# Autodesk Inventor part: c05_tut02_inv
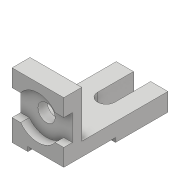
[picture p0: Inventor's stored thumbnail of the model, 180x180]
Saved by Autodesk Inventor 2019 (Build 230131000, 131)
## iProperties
Created: 2017-04
Part Number: c05_tut02_inv
Material: Generic
Document SubType Name: Modeling
Designer: CADCIM 00
Density: 1 g/cm^3
Appearance: Default
Author: CADCIM 00
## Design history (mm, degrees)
sketch "Sketch1"
  geometry: L1 (0, 0)-(0, 90); L2 (0, 90)-(25, 90); L3 (25, 90)-(25, 25); L4 (25, 25)-(145, 25); L5 (145, 25)-(145, 0); L6 (145, 0)-(0, 0)
  constraints: 12 end point, 6 perpendicular, 1 vertical
  dimensions: "d0" = 90 distance of L1.start L1.end; "d1" = 25 distance of L1.end L2.end; "d2" = 145 distance of L5.end L1.start
extrude "Extrusion1" new body sketch "Sketch1" stored distance "d3" = 72; taper "d4" = 0 deg
sketch "Sketch2"
  geometry: L1 (0, 0)-(0, 145) reference; L2 (0, 0)-(-6, 0); L3 (-6, 0)-(-6, 72); L4 (-6, 72)-(0, 72); L5 (0, 72)-(0, 0)
  constraints: 8 end point, 2 parallel, 1 horizontal, 1 perpendicular
  dimensions: "d5" = 72 distance between parallel lines of L4 L2; "d6" = 6 distance between parallel lines of L1 L3
extrude "Extrusion2" cut sketch "Sketch2" distance "d7" = 50; taper "d8" = 0 deg
sketch "Sketch3"
  geometry: L1 (0, 0)-(0, -65) reference; L2 (72, -65)-(72, 0) reference; L3 (72, -24)-(72, -60); L4 (0, -60)-(0, -24); L5 (0, -24)-(12, -24); L6 (60, -24)-(72, -24); L7 (72, -60)-(60, -60); L8 (12, -60)-(0, -60); L9 (72, -90)-(22, -90) reference; L10 (0, -90)-(22, -90) reference; A1 r 30 centre (36, -42) between (12, -60) and (60, -60); A2 r 30 centre (36, -42) between (60, -24) and (12, -24); 1 further point
  constraints: 12 end point, 5 parallel, 4 point on circle, 2 centre point, 2 collinear, 2 horizontal, 2 perpendicular, 2 point on line, 1 concentric
  dimensions: "d9" = 30 radius of A2; "d10" = 48 distance from line of L9 A1.centre; "d11" = 36 distance from line of L1 A1.centre; "d12" = 36 distance between parallel lines of L8 L5; "d13" = 30 distance between parallel lines of L10 L8
extrude "Extrusion3" cut sketch "Sketch3" distance "d14" = 12; taper "d15" = 0 deg
sketch "Sketch4"
  geometry: C1 r 12 at (36, -42); A1 r 30 centre (36, -42) between (60, -24) and (12, -24) reference; 1 further point
  constraints: 1 centre point, 1 concentric
  dimensions: "d16" = 24 diameter of C1
extrude "Extrusion4" cut sketch "Sketch4" stored distance "d17" = 12; taper "d18" = 0 deg
sketch "Sketch5"
  geometry: L1 (36, 119.693)-(36, 70); L2 (24, 119.693)-(24, 70); L3 (48, 70)-(48, 120); L4 (72, 120)-(0, 120) reference; L5 (24.004, 120)-(48, 120); L6 (72, 120)-(0, 120) reference; L7 (72, 120)-(72, 0) reference; A1 r 12 centre (36, 70) between (24, 70) and (48, 70); A2 r 12 centre (36, 119.693) between (24.004, 120) and (24, 119.693); 2 further points
  constraints: 10 end point, 4 point on circle, 3 tangent, 2 centre point, 2 point on line, 2 vertical, 1 collinear, 1 midpoint, 1 parallel
  dimensions: "d19" = 50 distance from line of L1.end L4; "d20" = 12 radius of A1; "d21" = 36 distance between parallel lines of L7 L1
extrude "Extrusion5" cut sketch "Sketch5" extent not by distance; stored distance "d22" = 12; taper "d23" = 0 deg
body "Solid1"
